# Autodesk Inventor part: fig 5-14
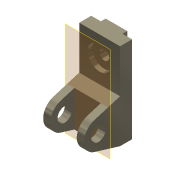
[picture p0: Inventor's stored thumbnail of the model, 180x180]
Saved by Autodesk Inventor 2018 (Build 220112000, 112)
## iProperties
Shininess: 65.0
Angle Display Precision: 2
Document Length Units: 11269
Document Angle Units: 11279
Document Time Units: 11290
Document Mass Units: 11283
Document Length Units Precision: 3
Document Angle Units Precision: 2
Compacted: False
Created: 2001-11
Part Number: fig 5-14
Document SubType Name: Modeling
Designer: Renu Muthoo
Density: 1 g/cm^3
Material: Generic
Appearance: Metal-Titanium (Polished)
Density: 0.0
Volumn: 0.0
Area: 0.0
PropertySet Name: Model Information
Control State: 0
Master: False
Checked Out: False
Author: Renu Muthoo
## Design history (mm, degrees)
node "Sketch1"
sketch "Sketch2"
  geometry: L1 (33.257, 104.664)-(33.257, -75.336); L2 (33.257, -75.336)-(8.257, -75.336); L3 (8.257, -75.336)-(-45.451, -59.045); L4 (-45.451, -1.628)-(8.257, 14.664); L5 (8.257, 14.664)-(8.257, 104.664); L6 (8.257, 104.664)-(33.257, 104.664); C1 r 15 at (-36.743, -30.336); A1 r 30 centre (-36.743, -30.336) between (-45.451, -1.628) and (-45.451, -59.045)
  constraints: 12 end point, 2 centre point, 2 equal length, 2 parallel, 2 point on circle, 2 tangent, 1 coincident, 1 perpendicular, 1 vertical
  dimensions: "d0" = 180 distance of L1.start L1.end; "d1" = 30 radius of A1; "d2" = 25 distance of L5.end L1.start; "d3" = 45 distance from line of L2 A1.centre; "d4" = 70 distance from line of L1 A1.centre; "d5" = 30 diameter of C1
extrude "Extrusion1" new body sketch "Sketch2" distance "d6" = 85; taper "d7" = 0 deg
workplane "Work Plane1"
sketch "Sketch3"
  geometry: L1 (15, 62.364)-(70, 62.364); L2 (70, 62.364)-(70, -52.386); L3 (70, -52.386)-(15, -52.386); L4 (15, -52.386)-(15, 62.364); L5 (0, -45)-(0, -28.708) reference
  constraints: 8 end point, 2 parallel, 1 horizontal, 1 perpendicular
  dimensions: "d8" = 55 distance of L1.start L1.end; "d9" = 15 distance between parallel lines of L5 L4
extrude "Extrusion2" cut sketch "Sketch3" distance "d10" = 50; taper "d11" = 0 deg
sketch "Sketch4"
  geometry: L1 (0, 25)-(85, 25) reference; L2 (0, 0)-(0, 25) reference; L3 (20, 25)-(65, 25); L4 (65, 25)-(65, 35); L5 (65, 35)-(20, 35); L6 (20, 35)-(20, 25)
  constraints: 8 end point, 2 parallel, 1 horizontal, 1 perpendicular, 1 point on line
  dimensions: "d12" = 45 distance of L4.end L5.end; "d13" = 10 distance of L3.end L4.end; "d14" = 20 distance between parallel lines of L2 L6
extrude "Extrusion3" join sketch "Sketch4" stored distance "d15" = 50; taper "d16" = 0 deg
sketch "Sketch5"
  geometry: L1 (85, 0)-(85, 90) reference; L2 (0, 90)-(85, 90) reference; 1 further point
  dimensions: "d17" = 42 distance from line of L2 point (42.5, 48); "d18" = 42.5 distance from line of L1 point (42.5, 48)
hole "Hole1" sketch "Sketch5" at (42.5, 48) diameter "d19" = 20; stored, may be unused: countersink angle "d23" = 82 deg, drill point angle "d25" = 118 deg; dims "d20" = 6, "d21" = 50, "d22" = 10, "d24" = 8
workplane "Work Plane6"
body "Solid1"
other parameters: "d26" = 0
